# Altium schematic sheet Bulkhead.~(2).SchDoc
size B; Organization: Monterey Bay Aquarium Research Institute; Address1: 7700 Sandholdt Rd; Address2: Moss Landing, CA 95039-9644; CompanyName: MBARI
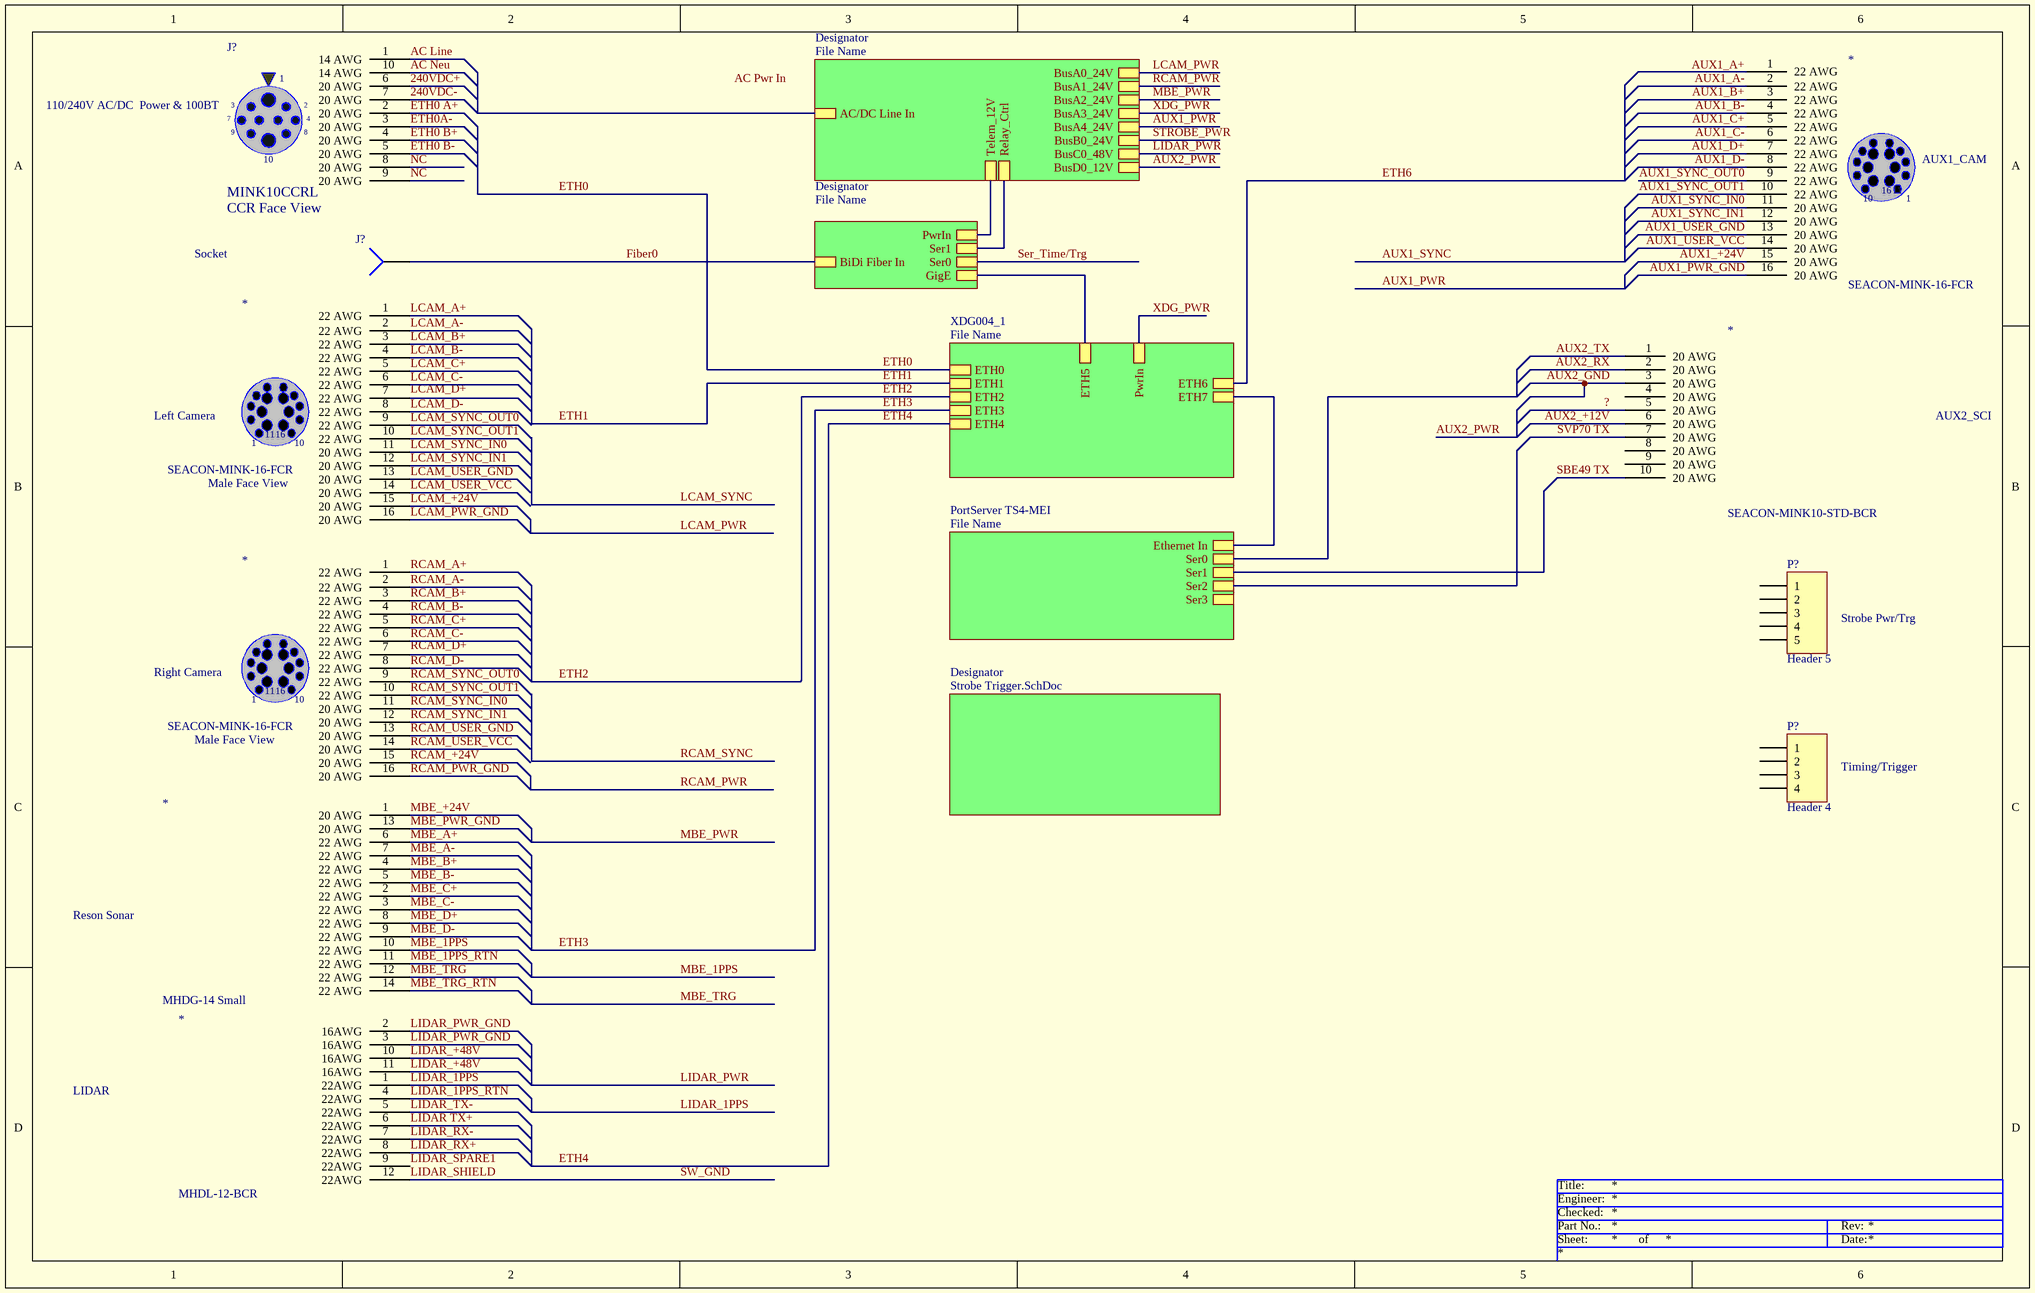
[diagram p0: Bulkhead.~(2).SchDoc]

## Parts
(Parts that share a designator on the sheet are numbered #1, #2 ... from top to bottom, then left to right.)
*#1  SEACON-MINK-16-FCR
*#2  SEACON-MINK-16-FCR
*#3  SEACON-MINK10-STD-BCR
*#4  SEACON-MINK-16-FCR
*#5  MHDG-14 Small
*#6  MHDL-12-BCR
J?#1  MINK10CCRL  View: CCR Face View
J?#2  Socket  [PIN1]
P?#1  Header 5  [HDR1X5]
P?#2  Header 4  [HDR1X4]

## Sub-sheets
Designator = File Name: AC/DC Line In, BusA0_24V, BusA1_24V, BusC0_48V, BusA2_24V, BusB0_24V, BusD0_12V, BusA3_24V, Telem_12V, Relay_Ctrl, BusA4_24V
Designator = File Name: BiDi Fiber In, GigE, Ser0, Ser1, PwrIn
Designator = Strobe Trigger.SchDoc: no entries
PortServer TS4-MEI = File Name: Ethernet In, Ser0, Ser1, Ser2, Ser3
XDG004_1 = File Name: ETH0, ETH1, ETH2, ETH3, ETH4, ETH5, ETH6, ETH7, PwrIn

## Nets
240VDC+: J?#1.6(20_AWG)
240VDC-: J?#1.7(20_AWG)
?: *#3.5(20_AWG)
AC Line: J?#1.1(14_AWG)
AC Neu: J?#1.10(14_AWG)
AUX1_+24V: *#1.15(20_AWG)
AUX1_A-: *#1.2(22_AWG)
AUX1_B+: *#1.3(22_AWG)
AUX1_B-: *#1.4(22_AWG)
AUX1_C+: *#1.5(22_AWG)
AUX1_C-: *#1.6(22_AWG)
AUX1_D+: *#1.7(22_AWG)
AUX1_D-: *#1.8(22_AWG)
AUX1_PWR_GND: *#1.16(20_AWG)
AUX1_SYNC_IN0: *#1.11(20_AWG)
AUX1_SYNC_IN1: *#1.12(20_AWG)
AUX1_SYNC_OUT0: *#1.9(22_AWG)
AUX1_SYNC_OUT1: *#1.10(22_AWG)
AUX1_USER_GND: *#1.13(20_AWG)
AUX1_USER_VCC: *#1.14(20_AWG)
AUX2_+12V: *#3.6(20_AWG)
AUX2_GND: *#3.3(20_AWG)
AUX2_RX: *#3.2(20_AWG)
AUX2_TX: *#3.1(20_AWG)
ETH0 A+: J?#1.2(20_AWG)
ETH0 B+: J?#1.4(20_AWG)
ETH0 B-: J?#1.5(20_AWG)
ETH0A-: J?#1.3(20_AWG)
Fiber0: J?#2.1 ; sheet Designator/BiDi Fiber In
LCAM_+24V: *#2.15(20_AWG)
LCAM_A+: *#2.1(22_AWG)
LCAM_A-: *#2.2(22_AWG)
LCAM_B+: *#2.3(22_AWG)
LCAM_B-: *#2.4(22_AWG)
LCAM_C+: *#2.5(22_AWG)
LCAM_C-: *#2.6(22_AWG)
LCAM_D-: *#2.8(22_AWG)
LCAM_PWR_GND: *#2.16(20_AWG)
LCAM_SYNC_IN0: *#2.11(20_AWG)
LCAM_SYNC_IN1: *#2.12(20_AWG)
LCAM_SYNC_OUT0: *#2.9(22_AWG)
LCAM_SYNC_OUT1: *#2.10(22_AWG)
LCAM_USER_GND: *#2.13(20_AWG)
LCAM_USER_VCC: *#2.14(20_AWG)
LIDAR TX+: *#6.6(22AWG)
LIDAR_1PPS: *#6.1(22AWG)
LIDAR_1PPS_RTN: *#6.4(22AWG)
LIDAR_+48V: *#6.10(16AWG) *#6.11(16AWG)
LIDAR_PWR_GND: *#6.2(16AWG) *#6.3(16AWG)
LIDAR_RX+: *#6.8(22AWG)
LIDAR_RX-: *#6.7(22AWG)
LIDAR_SHIELD: *#6.12(22AWG)  [also labelled SW_GND]
LIDAR_SPARE1: *#6.9(22AWG)
LIDAR_TX-: *#6.5(22AWG)
MBE_1PPS: *#5.10(22_AWG)
MBE_1PPS_RTN: *#5.11(22_AWG)
MBE_+24V: *#5.1(20_AWG)
MBE_A+: *#5.6(22_AWG)
MBE_A-: *#5.7(22_AWG)
MBE_B+: *#5.4(22_AWG)
MBE_B-: *#5.5(22_AWG)
MBE_C+: *#5.2(22_AWG)
MBE_C-: *#5.3(22_AWG)
MBE_D+: *#5.8(22_AWG)
MBE_D-: *#5.9(22_AWG)
MBE_PWR_GND: *#5.13(20_AWG)
MBE_TRG: *#5.12(22_AWG)
MBE_TRG_RTN: *#5.14(22_AWG)
NC: J?#1.8(20_AWG) J?#1.9(20_AWG)
RCAM_+24V: *#4.15(20_AWG)
RCAM_A+: *#4.1(22_AWG)
RCAM_A-: *#4.2(22_AWG)
RCAM_B+: *#4.3(22_AWG)
RCAM_B-: *#4.4(22_AWG)
RCAM_C+: *#4.5(22_AWG)
RCAM_C-: *#4.6(22_AWG)
RCAM_D-: *#4.8(22_AWG)
RCAM_PWR_GND: *#4.16(20_AWG)
RCAM_SYNC_IN0: *#4.11(20_AWG)
RCAM_SYNC_IN1: *#4.12(20_AWG)
RCAM_SYNC_OUT0: *#4.9(22_AWG)
RCAM_SYNC_OUT1: *#4.10(22_AWG)
RCAM_USER_GND: *#4.13(20_AWG)
RCAM_USER_VCC: *#4.14(20_AWG)
SBE49 TX: *#3.10(20_AWG)
SVP70 TX: *#3.7(20_AWG)

Not connected (* = marked no-connect by the designer): *#1 1(22_AWG); *#2 7(22_AWG); *#3 4(20_AWG) 8(20_AWG) 9(20_AWG); *#4 7(22_AWG); P?#1 1 2 3 4 5; P?#2 1 2 3 4

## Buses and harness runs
bus AUX1_PWR
bus AUX1_PWR = sheet Designator/BusA4_24V
bus AUX1_SYNC
bus AUX2_PWR
bus AUX2_PWR = sheet Designator/BusD0_12V
bus ETH0 = sheet XDG004_1/ETH0
bus ETH1 = sheet XDG004_1/ETH1
bus ETH2 = sheet XDG004_1/ETH2
bus ETH3 = sheet XDG004_1/ETH3
bus ETH4 = sheet XDG004_1/ETH4
bus ETH6 = sheet XDG004_1/ETH6
bus LCAM_PWR
bus LCAM_PWR = sheet Designator/BusA0_24V
bus LCAM_SYNC
bus LIDAR_1PPS
bus LIDAR_PWR
bus LIDAR_PWR = sheet Designator/BusC0_48V
bus MBE_1PPS
bus MBE_PWR
bus MBE_PWR = sheet Designator/BusA2_24V
bus MBE_TRG
bus RCAM_PWR
bus RCAM_PWR = sheet Designator/BusA1_24V
bus RCAM_SYNC
bus Ser_Time/Trg = sheet Designator/Ser0
bus sheet Designator/GigE = sheet XDG004_1/ETH5
bus sheet Designator/PwrIn = sheet Designator/Telem_12V
bus sheet Designator/Relay_Ctrl = sheet Designator/Ser1
bus sheet PortServer TS4-MEI/Ethernet In = sheet XDG004_1/ETH7
bus STROBE_PWR = sheet Designator/BusB0_24V
bus XDG_PWR = sheet Designator/BusA3_24V
bus XDG_PWR = sheet XDG004_1/PwrIn

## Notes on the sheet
- 110/240V AC/DC  Power & 100BT
- AUX1_CAM
- Left Camera
- AUX2_SCI
- Male Face View
- Strobe Pwr/Trg
- Right Camera
- Timing/Trigger
- Reson Sonar
- LIDAR
- Labels drawn without touching a wire or pin: AC Pwr In, AUX1_A+, LCAM_D+, RCAM_D+

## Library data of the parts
*#1 *#2 *#4 = SEACON-MINK-16-FCR: Seacon MINK-16 FCR
*#3 = SEACON-MINK10-STD-BCR: Seacon MINK10 BCR Standard Length
*#6 = MHDL-12-BCR: Impulse MHDL12 BCR
J?#1 = SEACON-MINK-10/L CCR (SMALL): Seacon MINK-10/L-CCR Molded to C/F Falmat Cable
P?#1 = Header 5: Header, 5-Pin
P?#2 = Header 4: Header, 4-Pin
